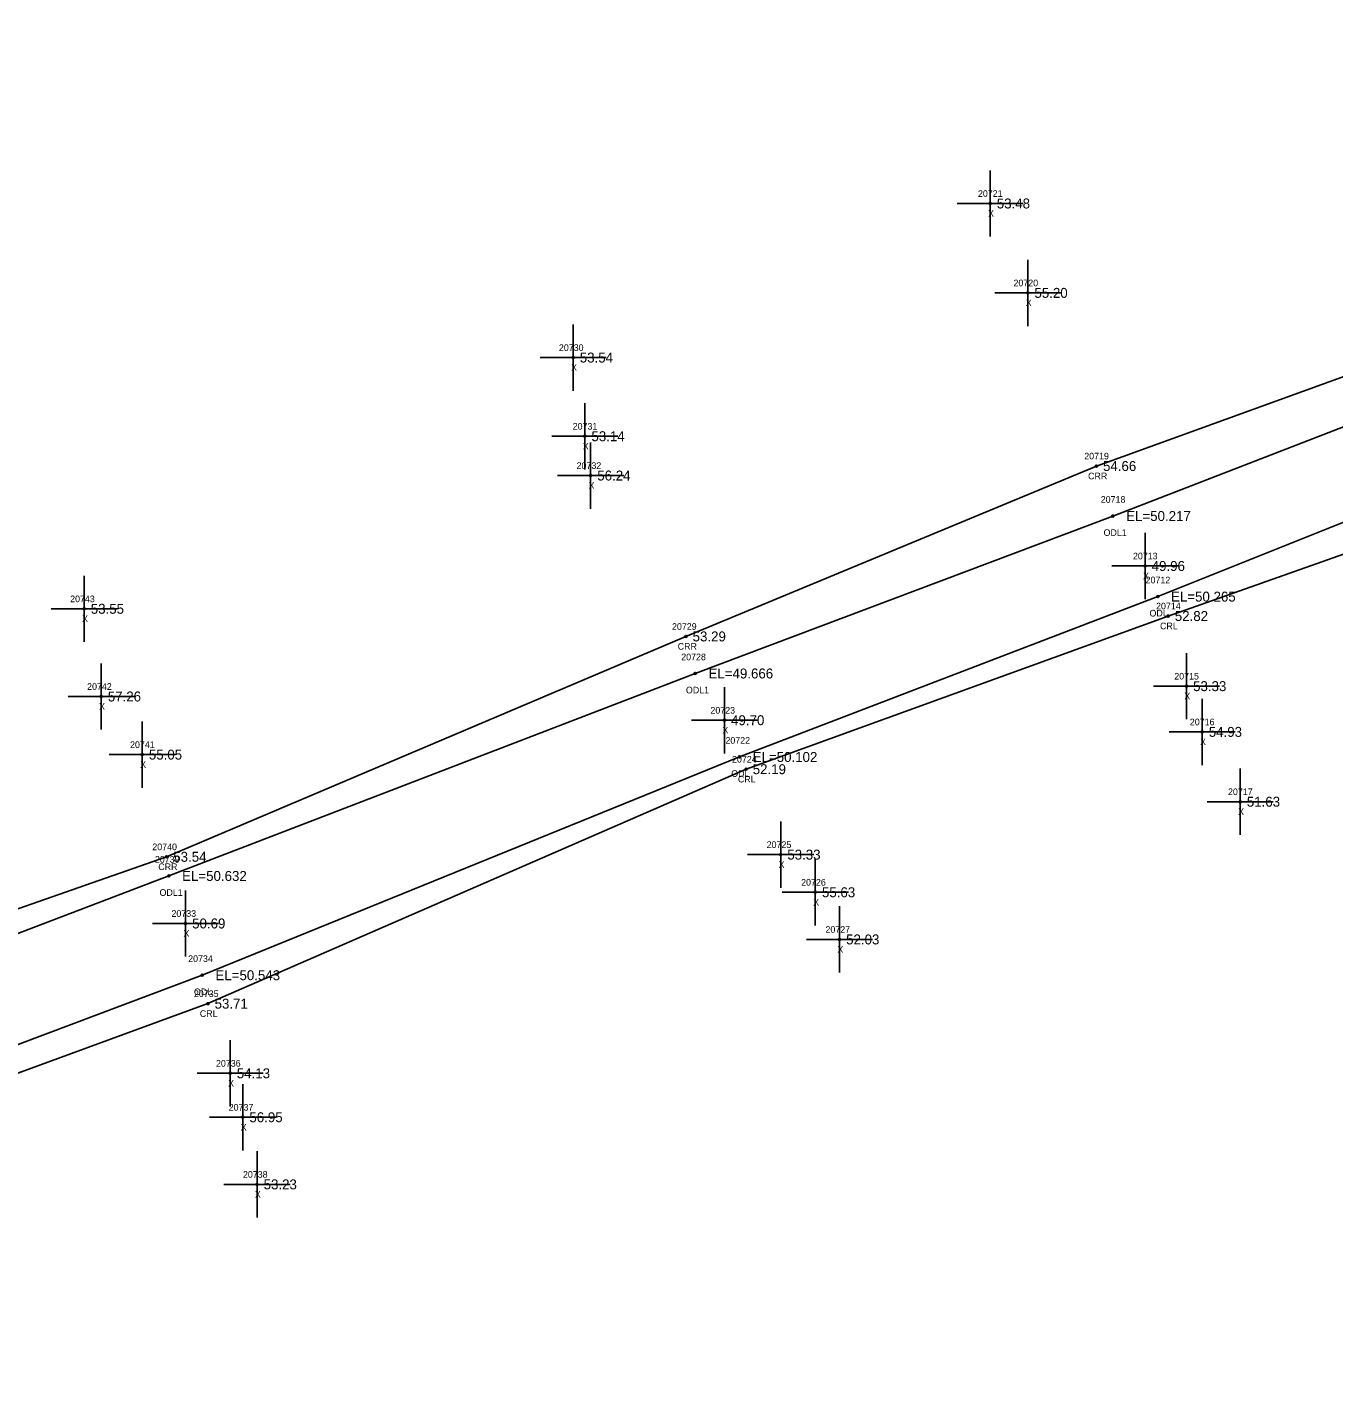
# Model space of a CAD drawing. Extents: x 2396547 to 2397655, y 770185 to 772649.
# Drawn here: x 2396705.8 to 2396902.9, y 771186.2 to 771393.4 of the extents above; entities that cross this region are included whole.
import ezdxf

# ---------------------------------------------------------------- set-up
doc = ezdxf.new("R2010")
doc.units = 0
for name, color, linetype in [('RD_EX_H2O', 7, 'Continuous'), ('RD_EX_H2O_txCode', 7, 'Continuous'), ('RD_EX_Misc', 7, 'Continuous'), ('RD_EX_Misc_txCode', 7, 'Continuous'), ('RD_EX_TX_H2O_ELEV', 7, 'Continuous'), ('RD_EX_TX_Misc_ELEV', 7, 'Continuous'), ('RD_SMD_Locator', 7, 'Continuous')]:
    doc.layers.add(name, color=color, linetype=linetype)

msp = doc.modelspace()

# ---------------------------------------------------------------- linework, layer by layer
at = {"layer": 'RD_EX_H2O'}
for points in [[(2397026.41, 771393.39), (2397025.73, 771381.74), (2396981.24, 771369.21), (2396933.35, 771351.16), (2396867.1, 771327.21), (2396805.16, 771301.5), (2396726.77, 771268.25), (2396662.72, 771245.88), (2396570.19, 771208.11)], [(2397042.3, 771381.6), (2397026.95, 771379.1), (2396982.27, 771366.23), (2396935.45, 771345.14), (2396869.6, 771319.67), (2396806.56, 771295.91), (2396727.11, 771265.36), (2396664.85, 771241.65), (2396575.64, 771198.56)], [(2397029.25, 771363), (2396987.12, 771353.36), (2396940.53, 771333.19), (2396876.37, 771307.51), (2396813.23, 771283.31), (2396732.14, 771250.38), (2396668.87, 771226.62), (2396581.1, 771189.01)], [(2397041.52, 771355.95), (2397038.66, 771356.79), (2397028.89, 771358.5), (2397025.33, 771358.42), (2397018.97, 771356.22), (2396990.02, 771346.89), (2396942.55, 771327.39), (2396877.94, 771304.58), (2396814.23, 771281.47), (2396733.01, 771246.09), (2396670.48, 771223.24), (2396582.44, 771186.21)]]:
    msp.add_lwpolyline(points, dxfattribs=at)
at = {"layer": 'RD_EX_Misc'}
for p, q in [((2396851.07, 771361.83), (2396851.07, 771371.83)), ((2396846.07, 771366.83), (2396856.07, 771366.83)), ((2396856.75, 771348.34), (2396856.75, 771358.34)), ((2396851.75, 771353.34), (2396861.75, 771353.34)), ((2396788.13, 771338.58), (2396788.13, 771348.58)), ((2396783.13, 771343.58), (2396793.13, 771343.58)), ((2396789.89, 771326.71), (2396789.89, 771336.71)), ((2396784.89, 771331.71), (2396794.89, 771331.71)), ((2396790.77, 771320.78), (2396790.77, 771330.78)), ((2396785.77, 771325.78), (2396795.77, 771325.78)), ((2396874.45, 771307.13), (2396874.45, 771317.13)), ((2396714.32, 771300.67), (2396714.32, 771310.67)), ((2396869.45, 771312.13), (2396879.45, 771312.13)), ((2396709.32, 771305.67), (2396719.32, 771305.67)), ((2396880.7, 771289), (2396880.7, 771299)), ((2396716.89, 771287.44), (2396716.89, 771297.44)), ((2396810.97, 771283.86), (2396810.97, 771293.86)), ((2396875.7, 771294), (2396885.7, 771294)), ((2396711.89, 771292.44), (2396721.89, 771292.44)), ((2396883.07, 771282.1), (2396883.07, 771292.1)), ((2396723.09, 771278.67), (2396723.09, 771288.67)), ((2396805.97, 771288.86), (2396815.97, 771288.86)), ((2396878.07, 771287.1), (2396888.07, 771287.1)), ((2396718.09, 771283.67), (2396728.09, 771283.67)), ((2396888.81, 771271.56), (2396888.81, 771281.56)), ((2396883.81, 771276.56), (2396893.81, 771276.56)), ((2396819.45, 771263.58), (2396819.45, 771273.58)), ((2396814.45, 771268.58), (2396824.45, 771268.58)), ((2396824.68, 771257.9), (2396824.68, 771267.9)), ((2396729.62, 771253.19), (2396729.62, 771263.19)), ((2396819.68, 771262.9), (2396829.68, 771262.9)), ((2396828.33, 771250.78), (2396828.33, 771260.78)), ((2396724.62, 771258.19), (2396734.62, 771258.19)), ((2396823.33, 771255.78), (2396833.33, 771255.78)), ((2396736.36, 771230.58), (2396736.36, 771240.58)), ((2396731.36, 771235.58), (2396741.36, 771235.58)), ((2396738.26, 771223.95), (2396738.26, 771233.95)), ((2396733.26, 771228.95), (2396743.26, 771228.95)), ((2396740.41, 771213.82), (2396740.41, 771223.82)), ((2396735.41, 771218.82), (2396745.41, 771218.82))]:
    msp.add_line(p, q, dxfattribs=at)
at = {"layer": 'RD_SMD_Locator'}
for centre in [(2396851.07, 771366.83), (2396856.75, 771353.34), (2396788.13, 771343.58), (2396789.89, 771331.71), (2396867.1, 771327.21), (2396790.77, 771325.78), (2396869.6, 771319.67), (2396874.45, 771312.13), (2396876.37, 771307.51), (2396714.32, 771305.67), (2396877.94, 771304.58), (2396805.16, 771301.5), (2396806.56, 771295.91), (2396880.7, 771294), (2396716.89, 771292.44), (2396810.97, 771288.86), (2396883.07, 771287.1), (2396723.09, 771283.67), (2396813.23, 771283.31), (2396814.23, 771281.47), (2396888.81, 771276.56), (2396726.77, 771268.25), (2396819.45, 771268.58), (2396727.11, 771265.36), (2396824.68, 771262.9), (2396729.62, 771258.19), (2396828.33, 771255.78), (2396732.14, 771250.38), (2396733.01, 771246.09), (2396736.36, 771235.58), (2396738.26, 771228.95), (2396740.41, 771218.82)]:
    msp.add_circle(centre, 0.15, dxfattribs=at)

# ---------------------------------------------------------------- texts
at = {"layer": 'RD_EX_H2O_txCode'}
for s, p in [('20719', (2396865.27, 771328.21)), ('CRR', (2396865.85, 771325.21)), ('20718', (2396867.76, 771321.67)), ('ODL1', (2396868.19, 771316.67)), ('20712', (2396874.53, 771309.51)), ('20714', (2396876.11, 771305.58)), ('ODL', (2396875.12, 771304.51)), ('20729', (2396803.05, 771302.5)), ('CRL', (2396876.71, 771302.58)), ('CRR', (2396803.91, 771299.5)), ('20728', (2396804.44, 771297.91)), ('ODL1', (2396805.15, 771292.91)), ('20722', (2396811.11, 771285.31)), ('20724', (2396812.11, 771282.47)), ('ODL', (2396811.99, 771280.31)), ('CRL', (2396813, 771279.47)), ('20740', (2396724.61, 771269.25)), ('20739', (2396725, 771267.36)), ('CRR', (2396725.51, 771266.25)), ('ODL1', (2396725.7, 771262.36)), ('20734', (2396730.02, 771252.38)), ('ODL', (2396730.89, 771247.38)), ('20735', (2396730.89, 771247.09)), ('CRL', (2396731.78, 771244.09))]:
    msp.add_text(s, height=1, dxfattribs=at).set_placement(p)
at = {"layer": 'RD_EX_Misc_txCode'}
for s, p in [('20721', (2396849.23, 771367.83)), ('X', (2396850.75, 771364.83)), ('20720', (2396854.59, 771354.34)), ('X', (2396856.44, 771351.34)), ('20730', (2396785.98, 771344.58)), ('X', (2396787.82, 771341.58)), ('20731', (2396788.06, 771332.71)), ('X', (2396789.58, 771329.71)), ('20732', (2396788.65, 771326.78)), ('X', (2396790.46, 771323.78)), ('20713', (2396872.62, 771313.13)), ('X', (2396874.14, 771310.13)), ('20743', (2396712.21, 771306.67)), ('X', (2396714.01, 771303.67)), ('20715', (2396878.86, 771295)), ('20742', (2396714.77, 771293.44)), ('X', (2396880.38, 771292)), ('X', (2396716.57, 771290.44)), ('20723', (2396808.85, 771289.86)), ('X', (2396810.66, 771286.86)), ('20716', (2396881.21, 771288.1)), ('20741', (2396721.25, 771284.67)), ('X', (2396882.75, 771285.1)), ('X', (2396722.77, 771281.67)), ('20717', (2396886.97, 771277.56)), ('X', (2396888.49, 771274.56)), ('20725', (2396817.34, 771269.58)), ('X', (2396819.14, 771266.58)), ('20726', (2396822.54, 771263.9)), ('X', (2396824.36, 771260.9)), ('20733', (2396727.5, 771259.19)), ('X', (2396729.31, 771256.19)), ('20727', (2396826.21, 771256.78)), ('X', (2396828.01, 771253.78)), ('20736', (2396734.22, 771236.58)), ('X', (2396736.05, 771233.58)), ('20737', (2396736.14, 771229.95)), ('X', (2396737.95, 771226.95)), ('20738', (2396738.29, 771219.82)), ('X', (2396740.09, 771216.82))]:
    msp.add_text(s, height=1, dxfattribs=at).set_placement(p)
at = {"layer": 'RD_EX_TX_H2O_ELEV'}
for s, p in [('54.66', (2396868.1, 771326.46)), ('EL=50.217', (2396871.6, 771318.92)), ('EL=50.265', (2396878.37, 771306.76)), ('52.82', (2396878.94, 771303.83)), ('53.29', (2396806.16, 771300.75)), ('EL=49.666', (2396808.56, 771295.16)), ('EL=50.102', (2396815.23, 771282.56)), ('52.19', (2396815.23, 771280.72)), ('53.54', (2396727.77, 771267.5)), ('EL=50.632', (2396729.11, 771264.61)), ('EL=50.543', (2396734.14, 771249.63)), ('53.71', (2396734.01, 771245.34))]:
    msp.add_text(s, height=1.5, dxfattribs=at).set_placement(p)
at = {"layer": 'RD_EX_TX_Misc_ELEV'}
for s, p in [('53.48', (2396852.07, 771366.08)), ('55.20', (2396857.75, 771352.59)), ('53.54', (2396789.13, 771342.83)), ('53.14', (2396790.89, 771330.96)), ('56.24', (2396791.77, 771325.03)), ('49.96', (2396875.45, 771311.38)), ('53.55', (2396715.32, 771304.92)), ('53.33', (2396881.7, 771293.25)), ('57.26', (2396717.89, 771291.69)), ('49.70', (2396811.97, 771288.11)), ('54.93', (2396884.07, 771286.35)), ('55.05', (2396724.09, 771282.92)), ('51.63', (2396889.81, 771275.81)), ('53.33', (2396820.45, 771267.83)), ('55.63', (2396825.68, 771262.15)), ('50.69', (2396730.62, 771257.44)), ('52.03', (2396829.33, 771255.03)), ('54.13', (2396737.36, 771234.83)), ('56.95', (2396739.26, 771228.2)), ('53.23', (2396741.41, 771218.07))]:
    msp.add_text(s, height=1.5, dxfattribs=at).set_placement(p)

doc.saveas('drawing.dxf')
